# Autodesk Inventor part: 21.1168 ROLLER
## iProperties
Created: 2007-03
Part Number: 21.1168 ROLLER
Document SubType Name: Modeling
Designer: Andy Moles
Material: Acetal Resin, Black
Mass: 0.928303 g
Surface Area: 5.66995 cm^2
Volume: 0.651441 cm^3
Density: 1.425 g/cm^3
Author: Andy Moles
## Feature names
1. Extrusion1
